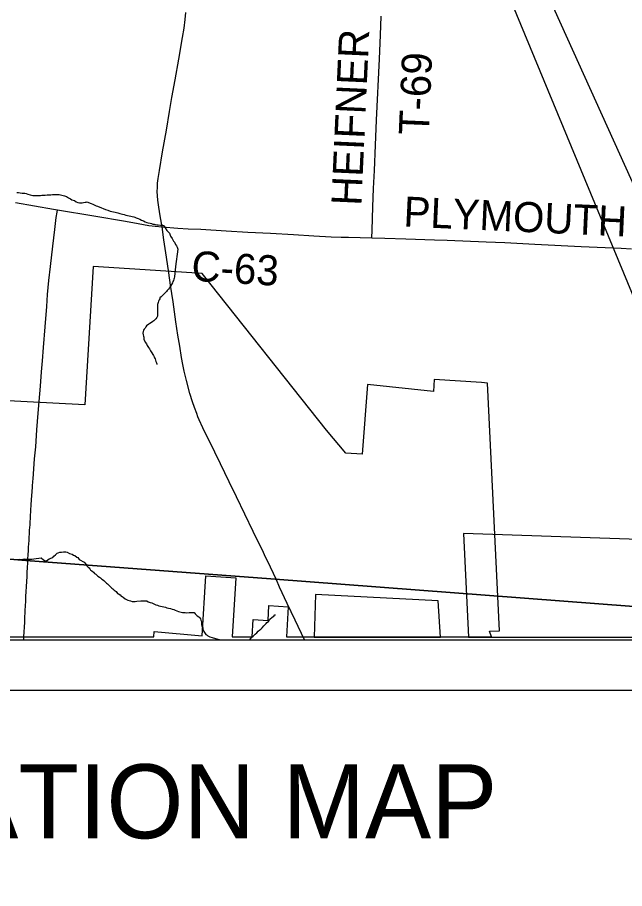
# Model space of a CAD drawing. Extents: x -5.4 to 49.9, y 13.2 to 48.4.
# Drawn here: x 29.446 to 30.593, y 40.173 to 41.82 of the extents above; entities that cross this region are included whole.
import ezdxf

# ---------------------------------------------------------------- set-up
doc = ezdxf.new("R2010")
doc.units = 0
for name, color, linetype in [('GM_X_Corporation', 7, 'Continuous'), ('GM_X_County_Road', 7, 'Continuous'), ('GM_X_County_Road_Text', 7, 'Continuous'), ('GM_X_Minor_River', 7, 'Continuous'), ('GM_X_State_Route', 7, 'Continuous'), ('GM_X_Township', 7, 'Continuous'), ('GM_X_Township_Road', 7, 'Continuous'), ('GM_X_Township_Road_Text', 7, 'Continuous'), ('SH_Data', 7, 'Continuous'), ('SH_Text', 7, 'Continuous')]:
    doc.layers.add(name, color=color, linetype=linetype)

msp = doc.modelspace()

# ---------------------------------------------------------------- linework, layer by layer
at = {"layer": 'GM_X_Corporation'}
for p, q in [((29.192, 40.6489), (29.7034, 40.6489)), ((29.8516, 40.6489), (29.8893, 40.6489)), ((29.9542, 40.6489), (30.3415, 40.6489)), ((30.0064, 40.6483), (30.2451, 40.6483)), ((30.2983, 40.6483), (32.5599, 40.6483))]:
    msp.add_line(p, q, dxfattribs=at)
for points in [[(30.3415, 40.6489), (30.3377, 40.6599), (30.3566, 40.6608), (30.3341, 41.129), (30.3225, 41.1298), (30.233, 41.136), (30.2316, 41.1133), (30.107, 41.1262), (30.0974, 40.9947), (30.0664, 40.9966), (30.03, 41.04), (29.7946, 41.3359), (29.5888, 41.3492), (29.5732, 41.088), (29.2219, 41.1059)], [(30.7487, 40.8288), (30.2884, 40.8443), (30.2983, 40.6483)], [(29.7034, 40.6489), (29.704, 40.6595), (29.7948, 40.651), (29.802, 40.7646), (29.8587, 40.761), (29.8516, 40.6489)], [(30.2451, 40.6483), (30.2407, 40.7171), (30.0092, 40.7292), (30.0064, 40.6483)], [(29.8893, 40.6489), (29.8911, 40.6819), (29.9194, 40.6801), (29.9209, 40.7085), (29.9573, 40.7062), (29.9542, 40.6489)]]:
    msp.add_lwpolyline(points, dxfattribs=at)
at = {"layer": 'GM_X_County_Road'}
for points in [[(29.4418, 41.47), (29.5141, 41.4579), (29.5212, 41.4567)], [(29.4677, 40.8331), (29.468, 40.8377), (29.4684, 40.8439), (29.4688, 40.8507), (29.4692, 40.8556), (29.4695, 40.8612), (29.4699, 40.8668), (29.4702, 40.8729), (29.4706, 40.8791), (29.4709, 40.8853), (29.4713, 40.8909), (29.4716, 40.8964), (29.472, 40.9014), (29.4723, 40.9057), (29.4726, 40.9099), (29.4729, 40.9143), (29.4732, 40.918), (29.4734, 40.9216), (29.4738, 40.926), (29.4741, 40.9303), (29.4744, 40.934), (29.4751, 40.9426), (29.4755, 40.9481), (29.4762, 40.9574), (29.4783, 40.9859), (29.4802, 41.0082), (29.4827, 41.0404), (29.4852, 41.072), (29.487, 41.0943), (29.4894, 41.1234), (29.4914, 41.15), (29.4931, 41.1711), (29.4951, 41.1959), (29.4983, 41.2355), (29.5011, 41.2739), (29.5028, 41.2964), (29.5052, 41.3229), (29.508, 41.3494), (29.5125, 41.388), (29.5161, 41.4192), (29.5191, 41.442), (29.5205, 41.4519), (29.5212, 41.4567)], [(29.5212, 41.4567), (29.59, 41.4451), (29.65, 41.4347), (29.6739, 41.4306), (29.6941, 41.427), (29.7057, 41.4253), (29.719, 41.4241)], [(29.719, 41.4241), (29.7485, 41.4218), (29.7684, 41.4208), (29.792, 41.4198), (29.8404, 41.4169), (29.8813, 41.4144), (29.9241, 41.4121), (29.9675, 41.4095), (30.006, 41.4073), (30.0388, 41.4054), (30.0574, 41.4047), (30.0711, 41.4045), (30.1156, 41.4036)], [(30.1156, 41.4036), (30.1401, 41.4031), (30.1798, 41.4018), (30.2338, 41.3998), (30.258, 41.3989), (30.3313, 41.3959), (30.3667, 41.3944), (30.4232, 41.3916), (30.5107, 41.3873), (30.5864, 41.3841), (30.6063, 41.383)], [(29.4655, 40.7922), (29.4657, 40.7968), (29.4661, 40.8042), (29.4665, 40.8123), (29.4668, 40.8185), (29.4672, 40.8253), (29.4676, 40.8315), (29.4677, 40.8331)], [(29.4578, 40.6437), (29.4581, 40.6492), (29.4595, 40.6771), (29.4598, 40.6845), (29.4604, 40.6969), (29.4605, 40.6994), (29.4609, 40.7075), (29.4614, 40.7174), (29.4618, 40.7254), (29.4624, 40.7347), (29.4629, 40.744), (29.4635, 40.7546), (29.4639, 40.7626), (29.4644, 40.7707), (29.4649, 40.78), (29.4653, 40.7893), (29.4655, 40.7922)]]:
    msp.add_lwpolyline(points, dxfattribs=at)
at = {"layer": 'GM_X_Minor_River'}
for points in [[(29.4447, 41.4895), (29.4477, 41.4891), (29.4511, 41.4887), (29.4545, 41.4882), (29.4572, 41.4882), (29.4598, 41.4878), (29.4621, 41.487), (29.4655, 41.4858), (29.4701, 41.4847), (29.475, 41.4838), (29.478, 41.4834), (29.4807, 41.4834), (29.4826, 41.4834), (29.4845, 41.4834), (29.4867, 41.4833), (29.4894, 41.4837), (29.4921, 41.484), (29.4955, 41.4844), (29.4981, 41.4843), (29.5019, 41.4847), (29.5046, 41.485), (29.5088, 41.485), (29.5122, 41.4853), (29.5145, 41.4853), (29.5171, 41.4856), (29.519, 41.4856), (29.522, 41.4856), (29.5243, 41.4852), (29.527, 41.4848), (29.5296, 41.4844), (29.5323, 41.4836), (29.5345, 41.4828), (29.5364, 41.482), (29.5383, 41.4816), (29.5402, 41.4801), (29.5425, 41.4789), (29.5462, 41.477), (29.5485, 41.4754), (29.5508, 41.4746), (29.5538, 41.4738), (29.5568, 41.4715), (29.5598, 41.4703), (29.5632, 41.4695), (29.5663, 41.4699), (29.5682, 41.4699), (29.5705, 41.4706), (29.5735, 41.4709), (29.5758, 41.4709), (29.5777, 41.4713), (29.5799, 41.4705), (29.5849, 41.4685), (29.5879, 41.4674), (29.5909, 41.4658), (29.5943, 41.4643), (29.5973, 41.4631), (29.6045, 41.46), (29.6079, 41.4588), (29.6121, 41.4572), (29.6166, 41.4556), (29.6211, 41.4541), (29.6272, 41.4529), (29.6306, 41.4521), (29.6332, 41.4513), (29.6355, 41.4509), (29.6393, 41.4497), (29.6416, 41.4489), (29.6442, 41.4481), (29.6472, 41.4473), (29.6503, 41.4465), (29.654, 41.4457), (29.6597, 41.4445), (29.6628, 41.4441), (29.6654, 41.4433), (29.6677, 41.4425), (29.6703, 41.441), (29.6737, 41.4398), (29.6767, 41.4386), (29.6801, 41.4371), (29.6839, 41.4355), (29.6873, 41.434), (29.6903, 41.4328), (29.693, 41.4316), (29.6968, 41.4312), (29.699, 41.4304), (29.7017, 41.4296), (29.7043, 41.4292), (29.7062, 41.4288), (29.7089, 41.428), (29.7115, 41.428), (29.7161, 41.4275), (29.7199, 41.4275), (29.7218, 41.4271), (29.7248, 41.4225), (29.7281, 41.4175), (29.7311, 41.4141), (29.733, 41.4125), (29.7352, 41.4068)], [(29.7352, 41.4068), (29.7378, 41.4022), (29.7408, 41.3973), (29.7423, 41.395), (29.7445, 41.3908), (29.746, 41.3881), (29.7475, 41.3858), (29.7482, 41.3839), (29.749, 41.382), (29.7443, 41.3491)], [(29.7443, 41.3491), (29.7428, 41.3297), (29.7417, 41.3275), (29.7412, 41.3252), (29.7404, 41.3229), (29.7393, 41.321), (29.7388, 41.3187), (29.7369, 41.3154), (29.7349, 41.3124), (29.7333, 41.309), (29.7314, 41.3067), (29.7286, 41.3037), (29.7271, 41.3018), (29.7248, 41.2996), (29.7189, 41.294), (29.7174, 41.2917), (29.7147, 41.2899), (29.7146, 41.288), (29.7134, 41.2861), (29.7123, 41.2835), (29.7115, 41.2812), (29.7106, 41.2774), (29.7106, 41.2751), (29.7105, 41.2725), (29.7105, 41.2687), (29.7104, 41.2664), (29.7104, 41.2645), (29.7107, 41.2614), (29.7107, 41.2588), (29.7106, 41.2553), (29.7094, 41.2531), (29.7075, 41.2501), (29.7036, 41.2467), (29.7013, 41.2456), (29.6989, 41.2434), (29.6962, 41.2415), (29.6943, 41.2404), (29.6897, 41.2371), (29.6881, 41.2352), (29.6869, 41.2329), (29.6854, 41.2311), (29.6842, 41.2292), (29.6834, 41.2265), (29.6829, 41.2235), (29.6833, 41.2201), (29.684, 41.2174), (29.6847, 41.2155), (29.6846, 41.2117), (29.6868, 41.2063), (29.6894, 41.2032), (29.6909, 41.2001), (29.6931, 41.1963), (29.6954, 41.1936), (29.6972, 41.1901), (29.6994, 41.1863), (29.7016, 41.1828), (29.7031, 41.1809), (29.7042, 41.1786), (29.705, 41.1766), (29.7057, 41.1747), (29.7064, 41.1721), (29.7075, 41.1697), (29.7082, 41.1675), (29.7089, 41.1655), (29.7093, 41.1648), (29.7093, 41.164)], [(29.4448, 40.7951), (29.4467, 40.7951), (29.4498, 40.7958), (29.4521, 40.7957), (29.4559, 40.7961), (29.4597, 40.7964), (29.4624, 40.7963), (29.4647, 40.7963), (29.4674, 40.7962), (29.4704, 40.7962), (29.4731, 40.7961), (29.4769, 40.7968), (29.4906, 40.7985), (29.4948, 40.795), (29.4982, 40.793), (29.5008, 40.7926), (29.5055, 40.7967), (29.5105, 40.7985), (29.5128, 40.7992), (29.5143, 40.8015), (29.5178, 40.8044), (29.5205, 40.8074), (29.5225, 40.8082), (29.5259, 40.8092), (29.5293, 40.8095), (29.5328, 40.8099), (29.5355, 40.8098), (29.5374, 40.8098), (29.5396, 40.809), (29.5442, 40.807), (29.5468, 40.8062), (29.5491, 40.8054), (29.5517, 40.8038), (29.554, 40.803), (29.5578, 40.7999), (29.5597, 40.7991), (29.5626, 40.7956), (29.5721, 40.7901), (29.575, 40.7863), (29.5769, 40.7836), (29.5791, 40.7812), (29.581, 40.7797), (29.5825, 40.7777), (29.584, 40.7754)], [(29.584, 40.7754), (29.5863, 40.7739), (29.5893, 40.7712), (29.5911, 40.7692), (29.5938, 40.7676), (29.596, 40.7661), (29.5979, 40.7641), (29.6005, 40.7622), (29.6024, 40.7606), (29.6043, 40.7587), (29.6065, 40.7575), (29.6088, 40.7556), (29.6122, 40.7525), (29.614, 40.7509), (29.6159, 40.7497), (29.6185, 40.7466), (29.6219, 40.7435), (29.6238, 40.7412), (29.6257, 40.74), (29.6287, 40.7373), (29.632, 40.7346), (29.635, 40.7311), (29.6369, 40.7303), (29.6396, 40.7287), (29.6418, 40.7264), (29.6437, 40.7252), (29.6456, 40.7241), (29.6493, 40.7213), (29.6516, 40.7198), (29.6546, 40.7186), (29.6569, 40.7178), (29.6595, 40.7173), (29.6626, 40.7161), (29.666, 40.7161), (29.6683, 40.716), (29.6713, 40.7167), (29.679, 40.717), (29.6843, 40.7173), (29.6878, 40.7172), (29.69, 40.7172), (29.6927, 40.7156), (29.6965, 40.7144), (29.6995, 40.7132), (29.7025, 40.712), (29.7048, 40.7112), (29.7074, 40.71), (29.7101, 40.7088), (29.7127, 40.708), (29.7162, 40.7072), (29.7192, 40.7063), (29.7222, 40.7059), (29.7253, 40.7051), (29.7283, 40.7043), (29.7313, 40.7035), (29.7347, 40.7026), (29.7378, 40.7014), (29.7412, 40.7006), (29.7438, 40.6994), (29.7472, 40.6982), (29.7499, 40.697), (29.7529, 40.6962), (29.7552, 40.6958), (29.7575, 40.6954), (29.7594, 40.6949), (29.7624, 40.6949), (29.7659, 40.6948), (29.7701, 40.6951), (29.7735, 40.6951), (29.7769, 40.6954), (29.7796, 40.6953), (29.7815, 40.6926), (29.7852, 40.6891), (29.7882, 40.6872), (29.7901, 40.6852), (29.7916, 40.6833), (29.7923, 40.6806), (29.7934, 40.6783), (29.7937, 40.6764), (29.7937, 40.6726), (29.7947, 40.6684), (29.7958, 40.6661), (29.7962, 40.6638), (29.7973, 40.6615), (29.798, 40.6592), (29.7995, 40.6573), (29.8017, 40.6538), (29.804, 40.6523), (29.8058, 40.6511), (29.8092, 40.6491), (29.8138, 40.6479), (29.8202, 40.6459), (29.8267, 40.6442), (29.8332, 40.6437), (29.8334, 40.6437)], [(29.8846, 40.6437), (29.8858, 40.6454), (29.8889, 40.6488), (29.8912, 40.6507), (29.8932, 40.6521), (29.8947, 40.654), (29.8982, 40.657), (29.9005, 40.66), (29.9036, 40.6622), (29.9059, 40.6637), (29.9083, 40.6663), (29.9114, 40.6697), (29.9133, 40.6716), (29.9157, 40.6742), (29.9172, 40.6764), (29.9199, 40.6783), (29.9227, 40.6824), (29.9269, 40.6862), (29.9304, 40.688), (29.932, 40.6906), (29.9331, 40.6906)]]:
    msp.add_lwpolyline(points, dxfattribs=at)
at = {"layer": 'GM_X_State_Route'}
msp.add_lwpolyline([(29.9882, 40.6437), (29.9704, 40.6809), (29.9556, 40.7124), (29.9412, 40.7434), (29.935, 40.7569), (29.9236, 40.7811), (29.9125, 40.8045), (29.9105, 40.8086), (29.8911, 40.8482), (29.8595, 40.9137), (29.8458, 40.9423), (29.8292, 40.9763), (29.8186, 40.9981), (29.7961, 41.0446), (29.7894, 41.0592), (29.7869, 41.0648), (29.7844, 41.0711), (29.78, 41.0828), (29.7765, 41.0934), (29.7718, 41.1095), (29.7652, 41.1341), (29.7608, 41.1515), (29.758, 41.1642), (29.7557, 41.177), (29.7523, 41.1985), (29.7491, 41.2194), (29.7453, 41.2446), (29.7399, 41.2827), (29.7352, 41.3141), (29.7319, 41.3374), (29.7275, 41.3669), (29.7226, 41.3995), (29.719, 41.4241), (29.7155, 41.445), (29.7129, 41.4615), (29.7111, 41.475), (29.7103, 41.483), (29.71, 41.491), (29.7101, 41.4984), (29.7107, 41.507), (29.7117, 41.5156), (29.714, 41.531), (29.7201, 41.5659), (29.7273, 41.6069), (29.7332, 41.6424), (29.7376, 41.6688), (29.7436, 41.7024), (29.7505, 41.741), (29.7577, 41.782), (29.7606, 41.7998), (29.7628, 41.8164), (29.7641, 41.8295)], dxfattribs=at)
at = {"layer": 'GM_X_Township'}
msp.add_line((28.3741, 40.6437), (31.4373, 40.6437), dxfattribs=at)
for points in [[(31.4373, 40.6437), (31.09, 40.6701), (29.9244, 40.7587), (29.4619, 40.7938), (28.3929, 40.8821), (28.3919, 40.8674), (28.3741, 40.6437)], [(28.3741, 40.6437), (28.3919, 40.8674), (28.3929, 40.8821), (29.4619, 40.7938), (29.9244, 40.7587), (31.09, 40.6701), (31.4373, 40.6437)]]:
    msp.add_lwpolyline(points, dxfattribs=at)
at = {"layer": 'GM_X_Township_Road'}
msp.add_lwpolyline([(30.1156, 41.4036), (30.116, 41.4183), (30.1173, 41.4624), (30.1188, 41.4965), (30.1201, 41.5307), (30.1221, 41.5785), (30.1244, 41.6262), (30.1297, 41.7417), (30.1316, 41.7864), (30.1331, 41.8224)], dxfattribs=at)
at = {"layer": 'SH_Data'}
msp.add_line((26.1653, 40.5483), (33.1653, 40.5483), dxfattribs=at)
msp.add_lwpolyline([(31.0729, 40.4803), (29.5617, 43.8236), (31.0729, 40.1733)], close=True, dxfattribs=at)

# ---------------------------------------------------------------- texts
at = {"layer": 'GM_X_County_Road_Text'}
for s, rotation, p in [('PLYMOUTH', 357.403, (30.1744, 41.425)), ('C-63', 356.5717, (29.7734, 41.3225))]:
    msp.add_text(s, height=0.05682, rotation=rotation, dxfattribs=at).set_placement(p)
at = {"layer": 'GM_X_Township_Road_Text'}
for s, rotation, p in [('HEIFNER', 87.3973, (30.0955, 41.4635)), ('T-69', 87.6012, (30.2229, 41.5969))]:
    msp.add_text(s, height=0.05682, rotation=rotation, dxfattribs=at).set_placement(p)
at = {"layer": 'SH_Text'}
msp.add_text('LOCATION MAP', height=0.14, dxfattribs=at).set_placement((28.9377, 40.2683))

doc.saveas('drawing.dxf')
